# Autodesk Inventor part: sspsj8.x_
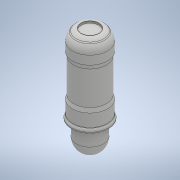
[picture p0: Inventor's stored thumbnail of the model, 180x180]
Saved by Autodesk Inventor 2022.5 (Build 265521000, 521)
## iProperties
Created: 2018-04
Part Number: sspsj8.x_
Material: 一般
Document SubType Name: Modeling
Designer: imaocorp
Density: 1 g/cm^3
Appearance: 既定
Sending System: SOLIDWORKS 2016-2016286
MC: AMD64
MC_MODEL: AMD64 Family 21 Model 2 Stepping 0, AuthenticAMD
OS: Windows_NT
FRU: Parasolid Version 28.0, build 224,  7-29-2016
FORMAT: text
GUISE: transmit
KEY: sspsj8
FILE: sspsj8.x_t
DATE: Wed Apr 25 10:15:43 2018
Author: imaocorp
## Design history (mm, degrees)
feature "Base1"
node "ソリッド1"
